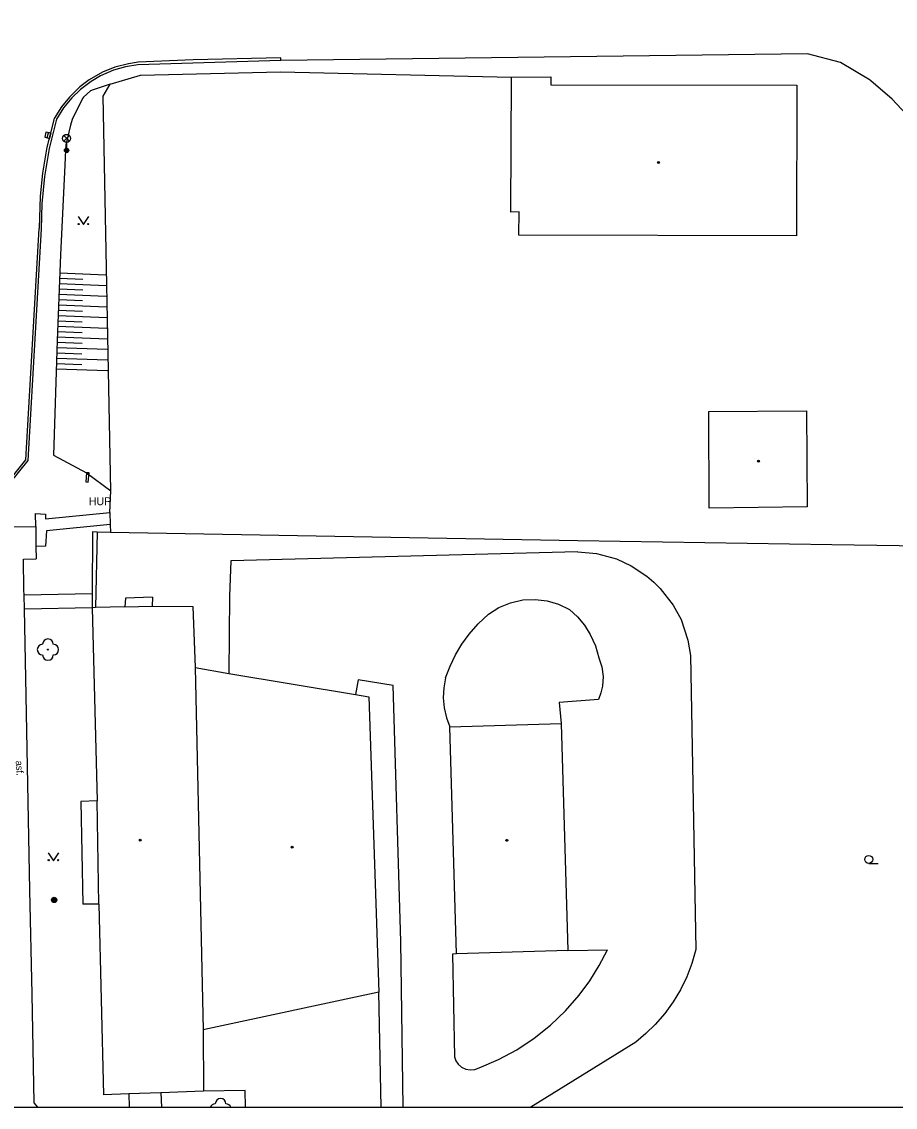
# Model space of a CAD drawing. Extents: x -599951 to -598963, y -1164095 to -1162939.
# Drawn here: x -599161.8 to -599079.8, y -1164094.7 to -1163992.9 of the extents above; entities that cross this region are included whole.
import ezdxf

# ---------------------------------------------------------------- set-up
doc = ezdxf.new("R2010")
doc.units = 0
for name, color, linetype in [('Level 10', 7, 'Continuous'), ('Level 11', 7, 'Continuous'), ('Level 14', 7, 'Continuous'), ('Level 15', 7, 'Continuous'), ('Level 22', 7, 'Continuous'), ('Level 24', 7, 'Continuous'), ('Level 25', 7, 'Continuous'), ('Level 27', 7, 'Continuous'), ('Level 33', 7, 'Continuous'), ('Level 36', 7, 'Continuous'), ('Level 39', 7, 'Continuous'), ('Level 40', 7, 'Continuous'), ('Level 41', 7, 'Continuous'), ('Level 5', 7, 'Continuous'), ('Level 7', 7, 'Continuous'), ('Vrstva 53', 7, 'Continuous')]:
    doc.layers.add(name, color=color, linetype=linetype)

msp = doc.modelspace()

# ---------------------------------------------------------------- linework, layer by layer
at = {"layer": 'Level 10'}
for points in [[(-599137.45, -1163996.55), (-599150.86, -1163996.96), (-599152.03, -1163997.16), (-599153.16, -1163997.48), (-599154.36, -1163998.01), (-599155.26, -1163998.53), (-599156.25, -1163999.28), (-599157.06, -1164000.05), (-599157.83, -1164000.99), (-599158.51, -1164002.07), (-599159.18, -1164004.81), (-599159.62, -1164007.45), (-599159.87, -1164010.01), (-599159.94, -1164012.34)], [(-599047.18, -1164021.12), (-599046.94, -1164024.17), (-599046.6, -1164028.52), (-599052.95, -1164028.76), (-599055.52, -1164028.6), (-599058.67, -1164027.63), (-599061.01, -1164026.19), (-599063.28, -1164023.52), (-599072.47, -1164009.11), (-599076.19, -1164004.41), (-599080.14, -1164000.19), (-599082.13, -1163998.46), (-599082.19, -1163998.41), (-599084.99, -1163996.74), (-599088.08, -1163995.94), (-599137.45, -1163996.55)], [(-599159.94, -1164012.34), (-599161.18, -1164034.05), (-599165.51, -1164039.38)]]:
    msp.add_lwpolyline(points, dxfattribs=at)
at = {"layer": 'Level 11'}
for p, q in [((-599125.99, -1164094.69), (-599126.22, -1164079.15)), ((-599128.06, -1164094.69), (-599128.27, -1164083.9)), ((-599104.19, -1164088.58), (-599114.02, -1164094.69)), ((-599148.7, -1164093.33), (-599148.64, -1164094.69)), ((-599160.26, -1164094.69), (-599160.6, -1164094.29)), ((-599151.73, -1164093.44), (-599151.67, -1164094.69))]:
    msp.add_line(p, q, dxfattribs=at)
for points in [[(-599150.84, -1163996.72), (-599151.76, -1163996.86), (-599153.03, -1163997.19), (-599154.2, -1163997.67), (-599155.43, -1163998.38), (-599156.31, -1163999.03), (-599157.29, -1163999.99), (-599158.03, -1164000.9), (-599158.71, -1164002)], [(-599137.45, -1163996.55), (-599137.45, -1163996.31), (-599145.69, -1163996.5), (-599150.84, -1163996.72)], [(-599158.71, -1164002), (-599159.39, -1164004.69), (-599159.8, -1164007.11), (-599160.03, -1164009.28), (-599160.13, -1164012.32)], [(-599165.72, -1164039.39), (-599161.36, -1164033.99), (-599160.13, -1164012.32)], [(-599160.45, -1164040.25), (-599160.48, -1164039.02), (-599159.53, -1164039.1), (-599159.53, -1164039.54), (-599153.49, -1164038.94), (-599153.41, -1164036.91)], [(-599153.49, -1164038.94), (-599153.45, -1164040.05), (-599153.42, -1164040.81)], [(-599163.42, -1164040.29), (-599160.45, -1164040.25)], [(-599160.45, -1164040.25), (-599160.42, -1164042.12), (-599160.4, -1164043.29)], [(-599153.45, -1164040.05), (-599159.45, -1164040.65), (-599159.53, -1164042.08), (-599160.42, -1164042.12)], [(-599155.12, -1164040.75), (-599155.14, -1164046.56), (-599155.14, -1164047.88)], [(-599154.7, -1164040.79), (-599155.12, -1164040.75)], [(-599154.7, -1164040.79), (-599154.83, -1164047.83)], [(-599109.62, -1164041.59), (-599153.42, -1164040.81), (-599154.7, -1164040.79)], [(-599085.8, -1164041.96), (-599109.62, -1164041.59)], [(-599066.4, -1164054.38), (-599066.7, -1164044.82), (-599066.86, -1164042.26), (-599085.8, -1164041.96)], [(-599161.59, -1164043.31), (-599160.4, -1164043.29)], [(-599160.6, -1164094.29), (-599160.79, -1164084.09), (-599160.99, -1164074.34), (-599161.36, -1164054.47), (-599161.51, -1164048.01), (-599161.54, -1164046.69), (-599161.55, -1164046.19), (-599161.59, -1164043.31)], [(-599109.61, -1164042.62), (-599142.16, -1164043.47), (-599142.27, -1164046.79), (-599142.35, -1164054.04)], [(-599109.61, -1164042.62), (-599107.87, -1164042.79), (-599105.98, -1164043.29), (-599104.6, -1164043.95), (-599103.13, -1164044.9), (-599102.49, -1164045.47), (-599101.9, -1164046.05), (-599100.66, -1164047.61), (-599099.94, -1164048.98), (-599099.29, -1164050.89), (-599099.04, -1164052.33)], [(-599155.14, -1164046.56), (-599161.54, -1164046.69)], [(-599118, -1164048.48), (-599117.01, -1164047.85), (-599115.92, -1164047.39), (-599114.78, -1164047.13), (-599113.6, -1164047.08), (-599112.49, -1164047.22), (-599111.42, -1164047.54), (-599110.41, -1164048.03)], [(-599155.14, -1164047.88), (-599161.51, -1164048.01)], [(-599152.09, -1164047.79), (-599149.52, -1164047.71)], [(-599122.01, -1164054.42), (-599121.59, -1164053.33), (-599121.08, -1164052.28), (-599120.48, -1164051.28), (-599119.8, -1164050.34), (-599118.95, -1164049.37), (-599118, -1164048.48)], [(-599110.41, -1164048.03), (-599109.66, -1164048.72), (-599109, -1164049.51), (-599108.45, -1164050.37), (-599107.96, -1164051.43), (-599107.63, -1164052.55)], [(-599107.63, -1164052.55), (-599107.36, -1164053.41), (-599107.25, -1164054.31), (-599107.31, -1164055.21), (-599107.46, -1164055.85), (-599107.69, -1164056.47)], [(-599099.04, -1164052.33), (-599098.55, -1164079.9)], [(-599130.22, -1164054.62), (-599130.47, -1164056.01)], [(-599126.92, -1164055.16), (-599130.22, -1164054.62)], [(-599122.01, -1164054.42), (-599122.18, -1164055.36), (-599122.23, -1164056.31), (-599122.14, -1164057.26), (-599121.93, -1164058.17), (-599121.61, -1164059.04)], [(-599126.22, -1164079.15), (-599126.92, -1164055.16)], [(-599129.22, -1164056.22), (-599128.27, -1164083.9)], [(-599107.69, -1164056.47), (-599111.36, -1164056.75), (-599111.18, -1164058.73)], [(-599110.55, -1164079.99), (-599120.98, -1164080.3), (-599121.61, -1164059.04), (-599111.18, -1164058.73), (-599110.55, -1164079.99)], [(-599154.53, -1164075.64), (-599154.7, -1164065.97)], [(-599118.86, -1164090.99), (-599117.06, -1164090.23), (-599115.34, -1164089.3), (-599113.7, -1164088.23), (-599112.18, -1164087.01), (-599110.76, -1164085.65), (-599109.48, -1164084.18), (-599108.49, -1164082.83), (-599107.61, -1164081.41), (-599106.84, -1164079.92)], [(-599110.55, -1164079.99), (-599106.84, -1164079.92)], [(-599098.55, -1164079.9), (-599098.92, -1164081.2), (-599099.4, -1164082.45), (-599099.98, -1164083.67), (-599100.68, -1164084.82), (-599101.47, -1164085.91), (-599102.35, -1164086.93), (-599103.24, -1164087.79), (-599104.19, -1164088.58)], [(-599120.98, -1164080.3), (-599121.38, -1164080.33), (-599121.19, -1164089.97)], [(-599121.19, -1164089.97), (-599121.05, -1164090.34), (-599120.82, -1164090.66), (-599120.52, -1164090.92), (-599120.13, -1164091.11), (-599119.7, -1164091.19), (-599119.27, -1164091.15), (-599118.86, -1164090.99)]]:
    msp.add_lwpolyline(points, dxfattribs=at)
at = {"layer": 'Level 14'}
for points in [[(-599153.45, -1163998.78), (-599155.06, -1163999.3), (-599155.3, -1163999.42), (-599155.97, -1164000.01), (-599156.06, -1164000.14), (-599157.02, -1164002.1), (-599157.2, -1164002.61), (-599157.61, -1164004.47), (-599157.65, -1164004.95), (-599157.72, -1164006.36), (-599158.12, -1164014.77), (-599158.45, -1164022.82), (-599158.78, -1164033.57)], [(-599158.78, -1164033.57), (-599155.69, -1164035.23)], [(-599155.69, -1164035.23), (-599153.41, -1164036.91)]]:
    msp.add_lwpolyline(points, dxfattribs=at)
at = {"layer": 'Level 15'}
for points in [[(-599158.21, -1164016.98), (-599156.03, -1164017.07)], [(-599158.19, -1164016.48), (-599153.86, -1164016.66)], [(-599158.25, -1164017.98), (-599156.04, -1164018.07)], [(-599158.23, -1164017.48), (-599153.84, -1164017.66)], [(-599158.29, -1164018.98), (-599156.06, -1164019.07)], [(-599158.27, -1164018.48), (-599153.83, -1164018.66)], [(-599158.33, -1164019.98), (-599156.07, -1164020.07)], [(-599158.31, -1164019.48), (-599153.81, -1164019.67)], [(-599158.37, -1164020.98), (-599156.08, -1164021.07)], [(-599158.35, -1164020.48), (-599153.79, -1164020.67)], [(-599158.42, -1164021.98), (-599156.09, -1164022.07)], [(-599158.4, -1164021.48), (-599153.78, -1164021.67)], [(-599158.45, -1164022.98), (-599156.1, -1164023.05)], [(-599158.44, -1164022.48), (-599153.76, -1164022.64)], [(-599158.48, -1164023.98), (-599156.11, -1164024.05)], [(-599158.47, -1164023.48), (-599153.75, -1164023.63)], [(-599158.52, -1164024.98), (-599156.12, -1164025.05)], [(-599158.5, -1164024.48), (-599153.73, -1164024.63)], [(-599158.53, -1164025.48), (-599153.71, -1164025.63)]]:
    msp.add_lwpolyline(points, dxfattribs=at)
at = {"layer": 'Level 22'}
msp.add_circle((-599159.3, -1164051.79), 0.05, dxfattribs=at)
for centre, start, end in [((-599159.8, -1164051.79), 90, 270), ((-599159.3, -1164051.29), 0, 180), ((-599158.8, -1164051.79), 270, 90), ((-599159.3, -1164052.29), 180, 0), ((-599143.61, -1164094.87), 90, 159.5127), ((-599143.11, -1164094.37), 0, 180), ((-599142.61, -1164094.87), 20.4873, 90)]:
    msp.add_arc(centre, 0.5, start, end, dxfattribs=at)
at = {"layer": 'Level 24'}
msp.add_lwpolyline([(-599155.76, -1164036.07), (-599155.52, -1164036.09), (-599155.45, -1164035.23), (-599155.69, -1164035.21), (-599155.76, -1164036.07)], dxfattribs=at)
at = {"layer": 'Level 25'}
for radius in [0.25, 0.2, 0.15, 0.1, 0.05]:
    msp.add_circle((-599158.72, -1164075.26), radius, dxfattribs=at)
at = {"layer": 'Level 27'}
msp.add_line((-599159.36, -1164003.81), (-599159.24, -1164003.33), dxfattribs=at)
msp.add_lwpolyline([(-599159.11, -1164003.87), (-599159, -1164003.38), (-599159.49, -1164003.27), (-599159.6, -1164003.76)], close=True, dxfattribs=at)
at = {"layer": 'Level 33'}
for p, q in [((-599157.82, -1164004.13), (-599157.29, -1164003.6)), ((-599157.82, -1164003.6), (-599157.29, -1164004.13)), ((-599157.55, -1164004.24), (-599157.55, -1164004.99))]:
    msp.add_line(p, q, dxfattribs=at)
for centre, radius in [((-599157.55, -1164003.86), 0.375), ((-599157.55, -1164004.99), 0.2), ((-599157.55, -1164004.99), 0.145), ((-599157.55, -1164004.99), 0.0876)]:
    msp.add_circle(centre, radius, dxfattribs=at)
at = {"layer": 'Level 36'}
msp.add_line((-599082.34, -1164071.84), (-599081.46, -1164071.84), dxfattribs=at)
for points in [[(-599156.47, -1164011.2), (-599155.97, -1164011.95), (-599155.47, -1164011.2)], [(-599159.28, -1164070.83), (-599158.78, -1164071.58), (-599158.28, -1164070.83)]]:
    msp.add_lwpolyline(points, dxfattribs=at)
for centre, radius in [((-599156.42, -1164011.9), 0.05), ((-599155.52, -1164011.9), 0.05), ((-599159.23, -1164071.53), 0.05), ((-599158.33, -1164071.53), 0.05), ((-599082.34, -1164071.46), 0.375)]:
    msp.add_circle(centre, radius, dxfattribs=at)
at = {"layer": 'Level 39'}
for centre, radius in [((-599102.06, -1164006.12), 0.09), ((-599102.06, -1164006.12), 0.0398), ((-599092.68, -1164034.12), 0.09), ((-599092.68, -1164034.12), 0.0398), ((-599150.64, -1164069.66), 0.09), ((-599150.64, -1164069.66), 0.0398), ((-599116.28, -1164069.67), 0.09), ((-599116.28, -1164069.67), 0.0398), ((-599136.39, -1164070.32), 0.09), ((-599136.39, -1164070.32), 0.0398)]:
    msp.add_circle(centre, radius, dxfattribs=at)
at = {"layer": 'Level 5'}
for points in [[(-599115.9, -1164010.78), (-599115.84, -1163998.12)], [(-599115.84, -1163998.12), (-599112.15, -1163998.09)], [(-599112.15, -1163998.09), (-599112.14, -1163998.84)], [(-599112.14, -1163998.84), (-599089.09, -1163998.89)], [(-599089.09, -1163998.89), (-599089.11, -1164013.01)], [(-599115.13, -1164010.75), (-599115.9, -1164010.78)], [(-599115.14, -1164012.93), (-599115.13, -1164010.75)], [(-599089.11, -1164013.01), (-599115.14, -1164012.93)], [(-599097.34, -1164029.47), (-599088.18, -1164029.39)], [(-599097.3, -1164038.52), (-599097.34, -1164029.47)], [(-599088.18, -1164029.39), (-599088.12, -1164038.42)], [(-599088.12, -1164038.42), (-599097.3, -1164038.52)], [(-599152.04, -1164046.97), (-599152.09, -1164047.79)], [(-599149.51, -1164046.88), (-599152.04, -1164046.97)], [(-599149.51, -1164046.88), (-599149.52, -1164047.71)], [(-599154.83, -1164047.83), (-599155.14, -1164047.88)], [(-599155.14, -1164047.88), (-599154.7, -1164065.97)], [(-599152.09, -1164047.79), (-599154.83, -1164047.83)], [(-599149.52, -1164047.71), (-599145.7, -1164047.75)], [(-599145.7, -1164047.75), (-599145.51, -1164053.46)], [(-599145.51, -1164053.46), (-599142.35, -1164054.04)], [(-599145.51, -1164053.46), (-599144.76, -1164087.42)], [(-599142.35, -1164054.04), (-599130.47, -1164056.01), (-599129.22, -1164056.22)], [(-599154.7, -1164065.97), (-599156.22, -1164066.03)], [(-599156.22, -1164066.03), (-599156.04, -1164075.65)], [(-599154.53, -1164075.64), (-599156.04, -1164075.65)], [(-599154.53, -1164075.64), (-599154.1, -1164093.53)], [(-599128.27, -1164083.9), (-599144.76, -1164087.42)], [(-599144.76, -1164087.42), (-599144.72, -1164093.19)], [(-599148.7, -1164093.33), (-599151.73, -1164093.44)], [(-599144.72, -1164093.19), (-599148.7, -1164093.33)], [(-599151.73, -1164093.44), (-599154.1, -1164093.53)]]:
    msp.add_lwpolyline(points, dxfattribs=at)
at = {"layer": 'Level 7'}
msp.add_line((-599140.77, -1164094.69), (-599140.82, -1164093.13), dxfattribs=at)
for points in [[(-599153.45, -1163998.78), (-599150.61, -1163997.93), (-599137.5, -1163997.62), (-599115.84, -1163998.12)], [(-599154.13, -1163999.91), (-599153.45, -1163998.78)], [(-599153.41, -1164036.91), (-599154.13, -1163999.91)], [(-599140.82, -1164093.13), (-599144.72, -1164093.19)]]:
    msp.add_lwpolyline(points, dxfattribs=at)
at = {"layer": 'Vrstva 53'}
msp.add_lwpolyline([(-599951.12, -1164094.69), (-598963.21, -1164094.69), (-598963.21, -1162939.4), (-599951.12, -1162939.4)], close=True, dxfattribs=at)

# ---------------------------------------------------------------- texts
at = {"layer": 'Level 40'}
msp.add_text('asf.', height=0.65, rotation=273.19, dxfattribs=at).set_placement((-599162.32, -1164062.22))
at = {"layer": 'Level 41'}
msp.add_text('HUP', height=0.75, dxfattribs=at).set_placement((-599155.48, -1164038.25))

doc.saveas('drawing.dxf')
